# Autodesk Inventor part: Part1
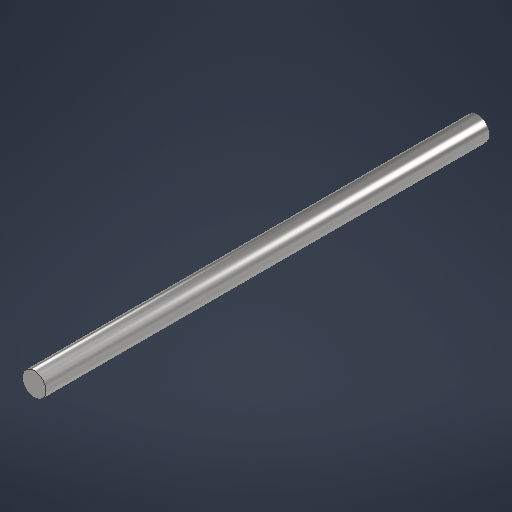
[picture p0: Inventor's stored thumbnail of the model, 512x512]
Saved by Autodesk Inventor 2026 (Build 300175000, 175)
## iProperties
Created: 2026-03
Part Number: Part1
Material: Stainless Steel
Document SubType Name: Modeling
Designer: Мельников Ю.С.
Density: 8 g/cm^3
Appearance: Semi-Polished
Author: Мельников Ю.С.
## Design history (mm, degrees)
sketch "Sketch1"
  geometry: C1 r 4 at (0, 0); 1 further point
  constraints: 1 centre point, 1 coincident
  dimensions: "d0" = 8 diameter of C1
extrude "Extrusion1" new body sketch "Sketch1" distance "d1" = 150; taper "d2" = 0 deg
body "Solid1"
